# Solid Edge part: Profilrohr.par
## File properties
Username: bmolnar
Dokumentum tartalom típus: 0
Author: bmolnar
Last saved by: bmolnar
Revision: 78
Sűrűség: 0,000 kg/m^3
Pontosság: 0,990
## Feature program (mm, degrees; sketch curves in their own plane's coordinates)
base feature "unnamed BaseFeature 1"
thread "unnamed Thread 1"
thread "Menet_4"  ThreadDepth = 9.3 mm
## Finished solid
Body 1: solid body, 177 faces, 454 edges, 298 vertices.
  Faces by surface: plane 102, cylinder 65, cone 6, torus 4
  Edges by curve: line 308, circle 136, curve on surface 7, spline 2, intersection 1
Bounding box of the edges (mm; curved faces can reach further): 124.000 x 131.000 x 71.000, from (-62, -62, 0) to (62, 69, 71).
Cylindrical faces by radius (mm): R0.2 x24, R2.625 x2, R5.5 x8, R5.7225 x4, R8.6 x16, R50 x1, R50.85 x2, R51.1 x2, R53.1 x2, R84 x4
Conical faces (half-angle, radius in mm at the cone's reference point): 30 deg R50.325 x2, 30 deg R51.283 x2, 45 deg R6.0725 x2
Toroidal faces (ring radius, tube radius in mm): R52.9 r0.2 x4
Planar faces by outward normal: +x 9, +y 11, +z 8, -x 9, -y 9, -z 8, oblique 48
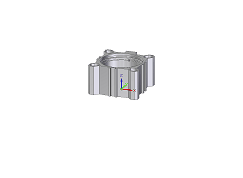
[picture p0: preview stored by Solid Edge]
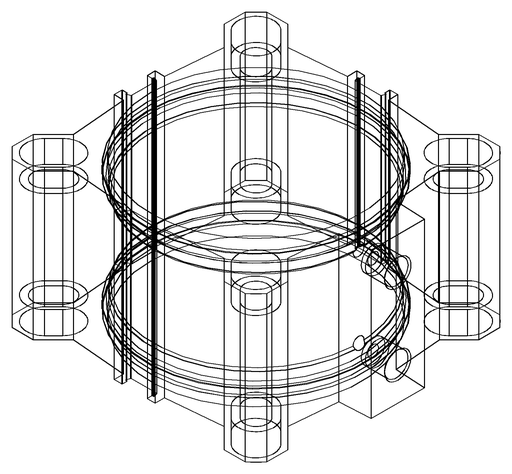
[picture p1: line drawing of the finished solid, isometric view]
